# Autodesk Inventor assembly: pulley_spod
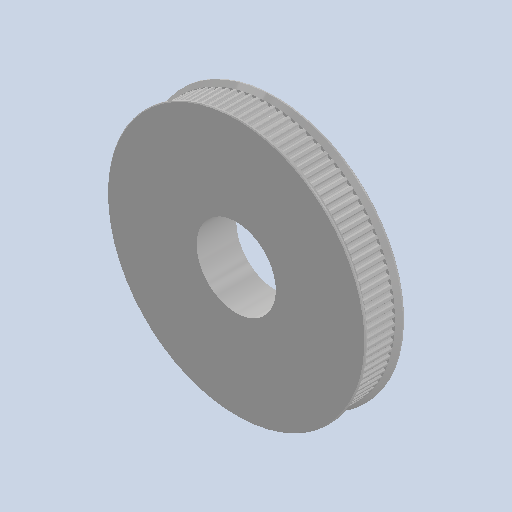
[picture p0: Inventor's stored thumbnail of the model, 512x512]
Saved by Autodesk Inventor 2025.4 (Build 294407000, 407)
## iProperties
Created: 2026-05
Part Number: pulley_spod
Document SubType Name: Assembly
Designer: AdminForWorker
Title: pulley_spod v1
Author: AdminForWorker
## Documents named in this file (2)
- c:\worker\convert-fusion-r03-cosv3\tmp\job-1\51\temp\files\a8907b3d-7d85-4bb5-924f-51d63d0d089f\48fd7209-9a5d-45a0-aedb-f7ac7c66cf0d.iam
- c:\worker\convert-fusion-r03-cosv3\tmp\job-1\51\temp\files\a8907b3d-7d85-4bb5-924f-51d63d0d089f\Component1.ipt
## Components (1 placed, 1 different names)
1. Component1:1
